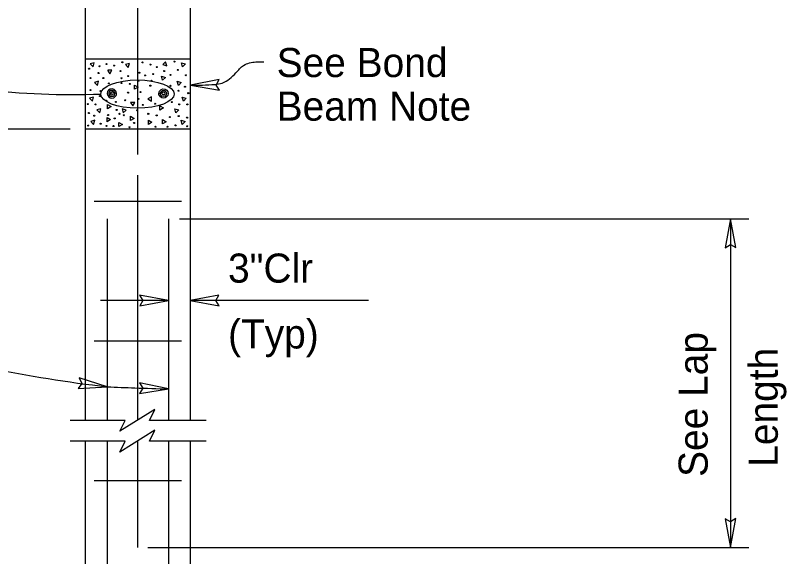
# Model space of a CAD drawing. Extents: x 0 to 2.83, y -0.03 to 1.83.
# Drawn here: x 1.4503 to 1.7955, y 1.1815 to 1.4236 of the extents above; entities that cross this region are included whole.
import ezdxf

# ---------------------------------------------------------------- set-up
doc = ezdxf.new("R2010")
doc.units = 0
for name, color, linetype in [('50', 7, 'Continuous'), ('51', 7, 'Continuous'), ('52', 7, 'Continuous'), ('54', 7, 'Continuous'), ('55', 7, 'Continuous'), ('57', 7, 'Continuous')]:
    doc.layers.add(name, color=color, linetype=linetype)

msp = doc.modelspace()

# ---------------------------------------------------------------- linework, layer by layer
at = {"layer": '50'}
for p, q in [((1.48159, 1.24241), (1.48159, 1.55013)), ((1.52854, 1.55013), (1.52854, 1.24241)), ((1.48159, 1.40422), (1.52854, 1.40422)), ((1.48159, 1.37292), (1.52854, 1.37292)), ((1.4855, 1.34054), (1.52463, 1.34054)), ((1.4855, 1.27804), (1.52463, 1.27804)), ((1.48159, 1.0136), (1.48159, 1.23312)), ((1.52854, 1.23312), (1.52854, 1.0136)), ((1.4855, 1.21554), (1.52463, 1.21554))]:
    msp.add_line(p, q, dxfattribs=at)
for centre in [(1.49104, 1.40188), (1.49812, 1.4027), (1.50719, 1.40263), (1.51068, 1.40167), (1.52146, 1.40301), (1.48322, 1.39982), (1.48791, 1.40088), (1.4944, 1.40118), (1.49726, 1.39871), (1.50573, 1.39801), (1.51355, 1.40055), (1.51686, 1.39877), (1.5229, 1.39925), (1.48391, 1.39562), (1.48747, 1.39787), (1.48961, 1.39562), (1.49774, 1.39553), (1.50074, 1.39652), (1.5083, 1.39682), (1.51193, 1.39742), (1.51964, 1.39701), (1.52659, 1.39687), (1.49209, 1.39322), (1.49774, 1.39337), (1.50144, 1.39299), (1.50537, 1.39443), (1.51064, 1.39221), (1.51111, 1.39438), (1.51971, 1.39214), (1.52616, 1.39174), (1.48384, 1.39024), (1.48829, 1.3898), (1.49299, 1.38887), (1.50067, 1.38909), (1.50629, 1.38932), (1.52327, 1.38992), (1.52766, 1.38886), (1.4881, 1.38755), (1.49104, 1.38548), (1.49524, 1.38492), (1.49939, 1.38569), (1.50537, 1.38631), (1.52024, 1.38484), (1.48266, 1.38398), (1.48616, 1.38379), (1.49557, 1.38139), (1.50477, 1.38119), (1.50728, 1.38358), (1.5128, 1.3841), (1.52359, 1.38385), (1.52722, 1.38379), (1.48316, 1.37997), (1.48554, 1.37878), (1.49175, 1.37908), (1.49469, 1.37754), (1.49688, 1.37961), (1.49879, 1.37898), (1.50975, 1.37961), (1.51349, 1.37889), (1.51943, 1.37815), (1.52334, 1.3786), (1.52709, 1.3779), (1.48284, 1.37433), (1.48841, 1.37515), (1.49104, 1.37423), (1.49416, 1.37416), (1.50335, 1.37551), (1.51301, 1.37382), (1.51829, 1.37382), (1.52196, 1.37446), (1.52716, 1.37408), (1.50132, 1.37362)]:
    msp.add_circle(centre, 0.000229, dxfattribs=at)
at = {"layer": '51'}
for p, q in [((1.50507, 1.36146), (1.50507, 1.54976)), ((1.49344, 1.38874), (1.49344, 1.38874)), ((1.49344, 1.38874), (1.49344, 1.38874)), ((1.49344, 1.38874), (1.49344, 1.38874)), ((1.51653, 1.38874), (1.51653, 1.38874)), ((1.51653, 1.38874), (1.51653, 1.38874)), ((1.50507, 1.24256), (1.50507, 1.35217)), ((1.49137, 1.33263), (1.49137, 1.24241)), ((1.51876, 1.33263), (1.51876, 1.24241)), ((1.49137, 1.23312), (1.49137, 1.0136)), ((1.50507, 1.18556), (1.50507, 1.23326)), ((1.51876, 1.23312), (1.51876, 1.0136))]:
    msp.add_line(p, q, dxfattribs=at)
for points in [[(1.49552, 1.38875), (1.49522, 1.3898), (1.4945, 1.39052), (1.49369, 1.3908), (1.4927, 1.39068), (1.49198, 1.39023), (1.49153, 1.38957), (1.49137, 1.3887), (1.49156, 1.38785), (1.49203, 1.38722), (1.49264, 1.38683), (1.49343, 1.38667), (1.49424, 1.38682), (1.49482, 1.38721), (1.49528, 1.38777), (1.49547, 1.38832), (1.49552, 1.38868), (1.4948, 1.38898), (1.49453, 1.38961), (1.49385, 1.39007), (1.49304, 1.39007), (1.4924, 1.38967), (1.49207, 1.38895), (1.49226, 1.38802), (1.49275, 1.38753), (1.49347, 1.38736), (1.49414, 1.38754), (1.49458, 1.38795), (1.49482, 1.38849), (1.49482, 1.38897), (1.494, 1.38914), (1.49363, 1.3894), (1.49317, 1.38937), (1.49282, 1.38902), (1.49283, 1.38844), (1.49319, 1.3881), (1.4937, 1.38811), (1.49407, 1.38847), (1.49412, 1.3889), (1.49402, 1.38914)], [(1.51445, 1.38875), (1.51475, 1.3898), (1.51547, 1.39052), (1.51628, 1.3908), (1.51727, 1.39068), (1.51799, 1.39023), (1.51844, 1.38957), (1.5186, 1.3887), (1.51841, 1.38785), (1.51794, 1.38722), (1.51734, 1.38683), (1.51654, 1.38667), (1.51574, 1.38682), (1.51515, 1.38721), (1.51469, 1.38777), (1.5145, 1.38832), (1.51445, 1.38868), (1.51517, 1.38898), (1.51544, 1.38961), (1.51612, 1.39007), (1.51693, 1.39007), (1.51757, 1.38967), (1.5179, 1.38895), (1.51771, 1.38802), (1.51722, 1.38753), (1.5165, 1.38736), (1.51584, 1.38754), (1.51539, 1.38795), (1.51515, 1.38849), (1.51515, 1.38897), (1.51597, 1.38914), (1.51634, 1.3894), (1.5168, 1.38937), (1.51715, 1.38902), (1.51714, 1.38844), (1.51678, 1.3881), (1.51627, 1.38811), (1.5159, 1.38847), (1.51585, 1.3889), (1.51595, 1.38914)]]:
    msp.add_lwpolyline(points, dxfattribs=at)
at = {"layer": '52'}
for p, q in [((1.48555, 1.40243), (1.48375, 1.40193)), ((1.48375, 1.40194), (1.48507, 1.40062)), ((1.48507, 1.40062), (1.48555, 1.40242)), ((1.50127, 1.40218), (1.49947, 1.40168)), ((1.49947, 1.40169), (1.50078, 1.40037)), ((1.50078, 1.40037), (1.50127, 1.40217)), ((1.51618, 1.40163), (1.51798, 1.40114)), ((1.51748, 1.40295), (1.51619, 1.40163)), ((1.51798, 1.40114), (1.51749, 1.40294)), ((1.52458, 1.40243), (1.52638, 1.40193)), ((1.52507, 1.40062), (1.52458, 1.40242)), ((1.52638, 1.40194), (1.52507, 1.40062)), ((1.49154, 1.39914), (1.49248, 1.39753)), ((1.4934, 1.39915), (1.49155, 1.39913)), ((1.49248, 1.39753), (1.4934, 1.39914)), ((1.51613, 1.39462), (1.51564, 1.39641)), ((1.51565, 1.3964), (1.51744, 1.39593)), ((1.51744, 1.39593), (1.51613, 1.39462)), ((1.48744, 1.39417), (1.48564, 1.39367)), ((1.48564, 1.39368), (1.48695, 1.39236)), ((1.48695, 1.39236), (1.48744, 1.39416)), ((1.50363, 1.39063), (1.50363, 1.3925)), ((1.50363, 1.39249), (1.50524, 1.39157)), ((1.50524, 1.39157), (1.50363, 1.39063)), ((1.5227, 1.39417), (1.5245, 1.39367)), ((1.52319, 1.39236), (1.5227, 1.39416)), ((1.5245, 1.39368), (1.52319, 1.39236)), ((1.48518, 1.3871), (1.48338, 1.3866)), ((1.48338, 1.38661), (1.48469, 1.38529)), ((1.48469, 1.38529), (1.48518, 1.38709)), ((1.5037, 1.38475), (1.50184, 1.38474)), ((1.50184, 1.38475), (1.50277, 1.38313)), ((1.50277, 1.38313), (1.5037, 1.38475)), ((1.50959, 1.38625), (1.5112, 1.38532)), ((1.51119, 1.38718), (1.5096, 1.38625)), ((1.5112, 1.38532), (1.5112, 1.38718)), ((1.52495, 1.3871), (1.52675, 1.3866)), ((1.52544, 1.38529), (1.52495, 1.38709)), ((1.52675, 1.38661), (1.52544, 1.38529)), ((1.48856, 1.38183), (1.48676, 1.38134)), ((1.48676, 1.38135), (1.48807, 1.38003)), ((1.48807, 1.38003), (1.48856, 1.38183)), ((1.49147, 1.38191), (1.49147, 1.38377)), ((1.49147, 1.38377), (1.49308, 1.38285)), ((1.49308, 1.38284), (1.49147, 1.38191)), ((1.49797, 1.3818), (1.49845, 1.38)), ((1.49977, 1.38132), (1.49797, 1.38179)), ((1.49845, 1.38), (1.49977, 1.38132)), ((1.51487, 1.38128), (1.51487, 1.38315)), ((1.51487, 1.38314), (1.51649, 1.38222)), ((1.51649, 1.38222), (1.51487, 1.38128)), ((1.52206, 1.38003), (1.52157, 1.38183)), ((1.52157, 1.38183), (1.52337, 1.38134)), ((1.52337, 1.38135), (1.52206, 1.38003)), ((1.49127, 1.3761), (1.49127, 1.37796)), ((1.49127, 1.37795), (1.49288, 1.37703)), ((1.5018, 1.37663), (1.5018, 1.3785)), ((1.5018, 1.37849), (1.50342, 1.37757)), ((1.50342, 1.37757), (1.5018, 1.37663)), ((1.48575, 1.3767), (1.48395, 1.37621)), ((1.48395, 1.37622), (1.48526, 1.3749)), ((1.48526, 1.3749), (1.48575, 1.3767)), ((1.49288, 1.37703), (1.49127, 1.3761)), ((1.4966, 1.37387), (1.4966, 1.37573)), ((1.4966, 1.37572), (1.49822, 1.3748)), ((1.49822, 1.3748), (1.4966, 1.37387)), ((1.50978, 1.37488), (1.50978, 1.37674)), ((1.50978, 1.37673), (1.51139, 1.37582)), ((1.51139, 1.37581), (1.50978, 1.37488)), ((1.51613, 1.37515), (1.51613, 1.37701)), ((1.51613, 1.377), (1.51774, 1.37608)), ((1.51774, 1.37608), (1.51613, 1.37515)), ((1.52487, 1.3749), (1.52439, 1.3767)), ((1.52439, 1.3767), (1.52619, 1.37621)), ((1.52619, 1.37622), (1.52487, 1.3749))]:
    msp.add_line(p, q, dxfattribs=at)
at = {"layer": '54'}
for points in [[(1.52862, 1.3925), (1.54162, 1.39013), (1.54011, 1.3925), (1.54147, 1.3949)], [(1.77037, 1.33263), (1.768, 1.31964), (1.77037, 1.32115), (1.77277, 1.31979)], [(1.51876, 1.29611), (1.50577, 1.29848), (1.50728, 1.29611), (1.50592, 1.29371)], [(1.52854, 1.29611), (1.54153, 1.29373), (1.54003, 1.29611), (1.54138, 1.29851)], [(1.49137, 1.25744), (1.4788, 1.26148), (1.47999, 1.25892), (1.47833, 1.25672)], [(1.51876, 1.25647), (1.50585, 1.25926), (1.50728, 1.25684), (1.50585, 1.25449)], [(1.77037, 1.18556), (1.77275, 1.19855), (1.77037, 1.19705), (1.76797, 1.1984)]]:
    msp.add_lwpolyline(points, close=True, dxfattribs=at)
at = {"layer": '55'}
for p, q in [((1.4228, 1.37292), (1.4748, 1.37292)), ((1.52377, 1.33263), (1.77856, 1.33263)), ((1.51876, 1.29611), (1.48839, 1.29611)), ((1.60839, 1.29611), (1.52854, 1.29611)), ((1.5127, 1.24729), (1.49696, 1.23753)), ((1.51026, 1.24241), (1.5127, 1.24729)), ((1.4994, 1.24241), (1.47471, 1.24241)), ((1.49696, 1.23753), (1.4994, 1.24241)), ((1.53566, 1.24241), (1.51026, 1.24241)), ((1.5127, 1.238), (1.49696, 1.22823)), ((1.51026, 1.23312), (1.5127, 1.238)), ((1.4994, 1.23312), (1.47471, 1.23312)), ((1.49696, 1.22823), (1.4994, 1.23312)), ((1.53566, 1.23312), (1.51026, 1.23312)), ((1.50954, 1.18556), (1.77856, 1.18556))]:
    msp.add_line(p, q, dxfattribs=at)
for centre, radius, start, end in [((1.47641, 1.74095), 0.35272, 254.7127, 271.9615), ((1.56297, 1.87203), 0.61875, 258.39913, 263.35539)]:
    msp.add_arc(centre, radius, start, end, dxfattribs=at)
msp.add_ellipse((1.5049, 1.38844), major_axis=(0.01641, 0), ratio=0.385371, dxfattribs=at)
for points in [[(1.52862, 1.3925), (1.5395, 1.39279), (1.54284, 1.39339), (1.54896, 1.39797), (1.55243, 1.40131), (1.55792, 1.40284), (1.56146, 1.40284)], [(1.49137, 1.25744), (1.50377, 1.25695), (1.51876, 1.25647)]]:
    msp.add_spline(points, degree=3, dxfattribs=at)
at = {"layer": '57'}
msp.add_line((1.77037, 1.33263), (1.77037, 1.18556), dxfattribs=at)

# ---------------------------------------------------------------- texts
for s, p in [('See Bond', (1.56721, 1.39606)), ('Beam Note', (1.56721, 1.37654)), ('3"Clr', (1.54544, 1.30406)), ('(Typ)', (1.54544, 1.27459))]:
    msp.add_text(s, height=0.013017, dxfattribs=at).set_placement(p)
for s, p in [('See Lap', (1.76015, 1.2171)), ('Length ', (1.79155, 1.22164))]:
    msp.add_text(s, height=0.013017, rotation=90, dxfattribs=at).set_placement(p)

doc.saveas('drawing.dxf')
